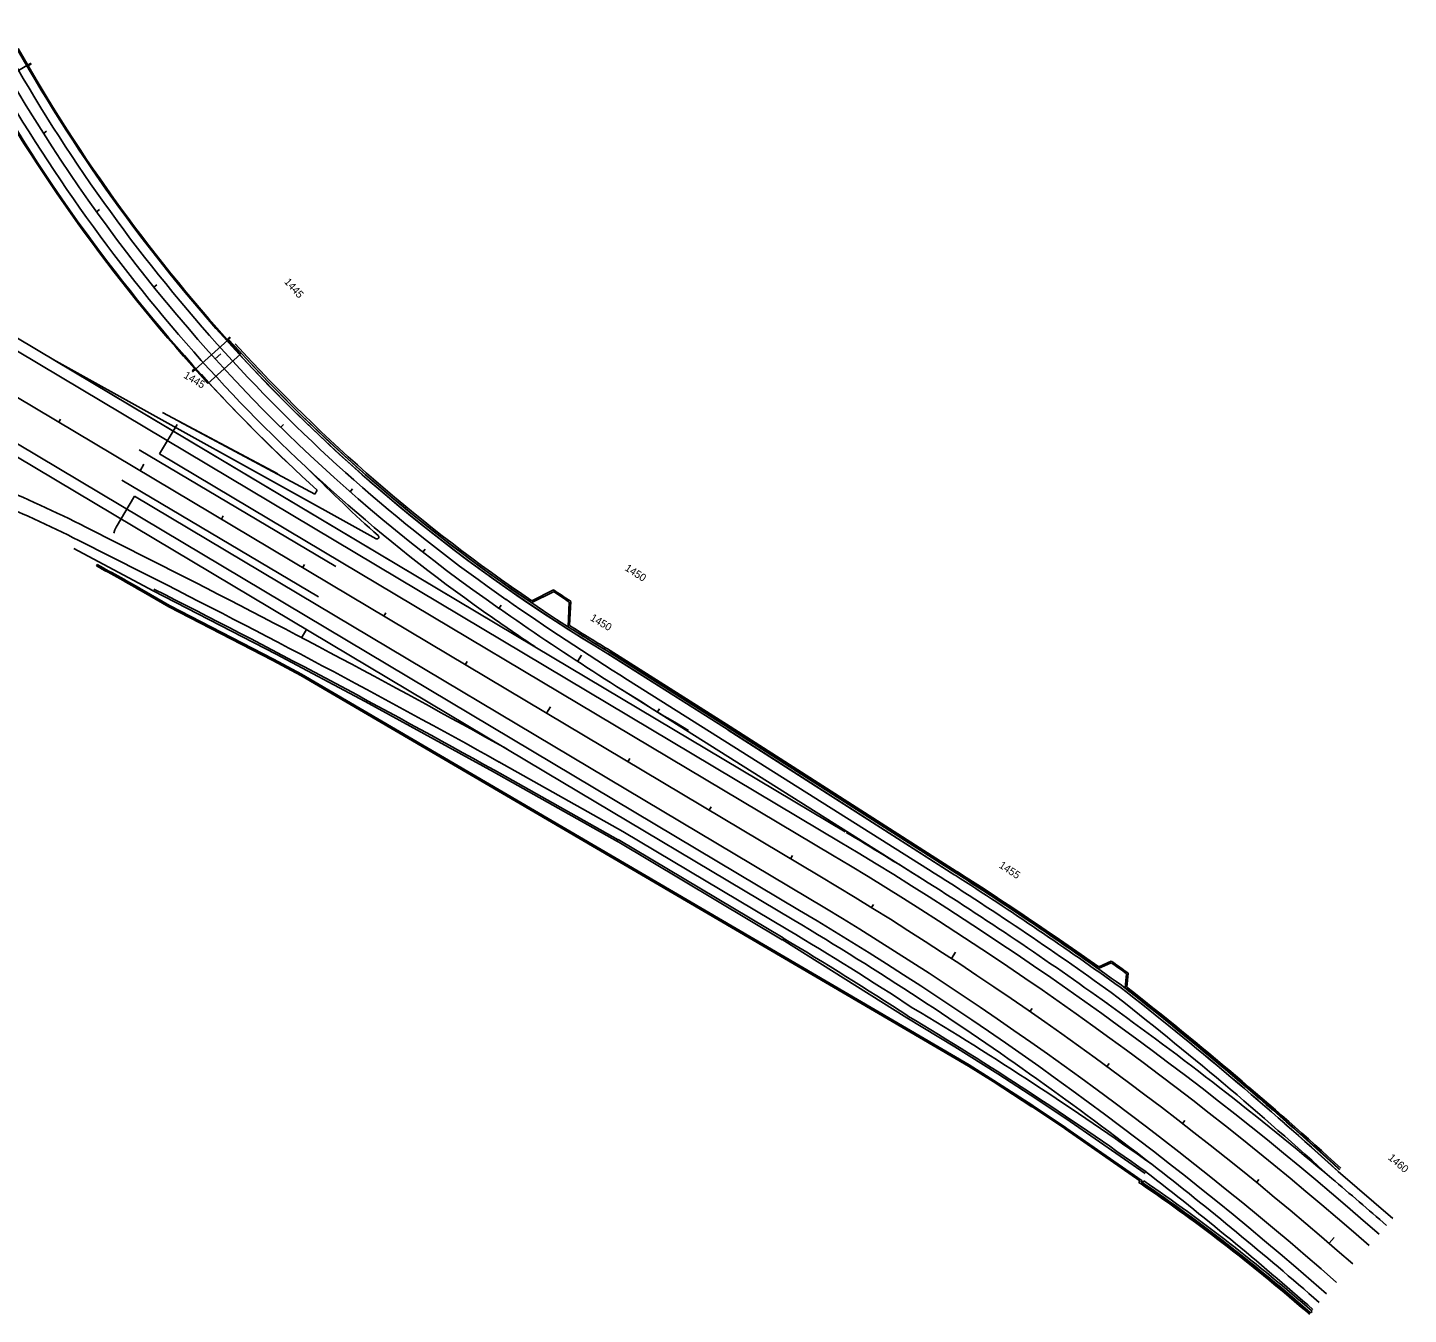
# Model space of a CAD drawing. Extents: x 2339272 to 2351734, y 366540 to 375057.
# Drawn here: x 2350276 to 2351734, y 366540 to 367900 of the extents above; entities that cross this region are included whole.
import ezdxf

# ---------------------------------------------------------------- set-up
doc = ezdxf.new("R2010")
doc.units = 0
for name, color, linetype in [('RD_HC_Cl', 7, 'Continuous'), ('RD_HC_Data_Tic', 7, 'Continuous'), ('RD_HC_TX_Sta50', 7, 'Continuous'), ('RD_PD_Bridge', 7, 'Continuous'), ('RD_PD_Final_LnLine', 7, 'Continuous'), ('RD_PD_Final_TrvlWay', 7, 'Continuous'), ('RD_PD_GR', 7, 'Continuous'), ('RD_PD_GrRail', 7, 'Continuous'), ('RD_PD_MedBWall', 7, 'Continuous'), ('RD_PD_NOISE-WALL-GM', 7, 'Continuous'), ('RD_PD_PaveShd', 7, 'Continuous')]:
    doc.layers.add(name, color=color, linetype=linetype)

msp = doc.modelspace()

# ---------------------------------------------------------------- linework, layer by layer
at = {"layer": 'RD_HC_Cl'}
msp.add_line((2346281.6, 369885.4), (2351112.4, 367003.2), dxfattribs=at)
for centre, radius, start, end in [((2351779.9, 368732.5), 1762, 199.588, 235.1808), ((2352718.5, 370082.1), 3405.9, 235.1808, 239.1785), ((2349155.3, 363723), 3819.7, 48.7231, 59.1785)]:
    msp.add_arc(centre, radius, start, end, dxfattribs=at)
at = {"layer": 'RD_HC_Data_Tic'}
for p, q in [((2350292.2, 367788.2), (2350295.6, 367790.4)), ((2350348.2, 367705.4), (2350351.4, 367707.7)), ((2350408.8, 367625.8), (2350411.9, 367628.3)), ((2350473.7, 367549.8), (2350479.7, 367555.2)), ((2350308.4, 367482.9), (2350310.4, 367486.3)), ((2350542.9, 367477.6), (2350545.7, 367480.5)), ((2350394.3, 367431.7), (2350398.4, 367438.5)), ((2350616.1, 367409.5), (2350618.7, 367412.5)), ((2350480.2, 367380.4), (2350482.2, 367383.9)), ((2350693, 367345.6), (2350695.5, 367348.7)), ((2350566, 367329.2), (2350568.1, 367332.6)), ((2350651.9, 367278), (2350654, 367281.4)), ((2350773.4, 367286.2), (2350775.7, 367289.5)), ((2350856.3, 367230.3), (2350860.7, 367237)), ((2350737.8, 367226.7), (2350739.8, 367230.2)), ((2350823.7, 367175.5), (2350827.8, 367182.4)), ((2350940.9, 367176.8), (2350942.9, 367180.3)), ((2350909.5, 367124.3), (2350911.6, 367127.7)), ((2350995.4, 367073), (2350997.5, 367076.5)), ((2351081.3, 367021.8), (2351083.3, 367025.2)), ((2351166.9, 366970.1), (2351169, 366973.5)), ((2351251.2, 366916.3), (2351255.6, 366923)), ((2351334.1, 366860.4), (2351336.4, 366863.6)), ((2351415.5, 366802.3), (2351417.8, 366805.5)), ((2351495.3, 366742), (2351497.7, 366745.2)), ((2351573.5, 366679.7), (2351576, 366682.8)), ((2351650.1, 366615.4), (2351655.3, 366621.5))]:
    msp.add_line(p, q, dxfattribs=at)
at = {"layer": 'RD_PD_Bridge'}
for p, q in [((2350235.5, 367837.1), (2350275.5, 367860.3)), ((2350486.9, 367569.7), (2350452.6, 367538.8)), ((2350500.4, 367554.9), (2350466, 367524))]:
    msp.add_line(p, q, dxfattribs=at)
for points in [[(2350275.5, 367860.3), (2350278.6, 367862.1), (2350279.1, 367861.2), (2350276, 367859.4)], [(2350486.3, 367570.4), (2350488.9, 367572.8), (2350489.5, 367572), (2350486.9, 367569.7)], [(2350449.3, 367537.2), (2350451.9, 367539.5), (2350452.6, 367538.8), (2350450, 367536.4)]]:
    msp.add_lwpolyline(points, close=True, dxfattribs=at)
for radius, start, end in [(1740, 209.4445, 222.6246), (1738.9, 209.4445, 222.6246), (1785.1, 209.4615, 222.6075), (1784, 209.4611, 222.6079)]:
    msp.add_arc((2351779.9, 368732.5), radius, start, end, dxfattribs=at)
at = {"layer": 'RD_PD_Final_LnLine'}
for p, q in [((2348620.9, 368538.6), (2351133.9, 367039.3)), ((2348577.9, 368466.5), (2351090.9, 366967.2)), ((2350811.2, 367245.8), (2351138.9, 367050.3)), ((2350902.7, 367200.6), (2351220.6, 367000.2))]:
    msp.add_line(p, q, dxfattribs=at)
for centre, radius, start, end in [((2351779.9, 368732.5), 1762, 199.588, 235.1808), ((2349155.3, 363723), 3873.7, 57.7811, 59.1785), ((2349155.3, 363723), 3861.7, 48.7231, 59.1785), ((2349155.3, 363723), 3873.7, 54.29, 57.7811), ((2349155.3, 363723), 3777.7, 48.7231, 59.1785), ((2349155.3, 363723), 3873.7, 49.8519, 54.3519)]:
    msp.add_arc(centre, radius, start, end, dxfattribs=at)
at = {"layer": 'RD_PD_Final_TrvlWay'}
for p, q in [((2348626.9, 368549), (2350811.2, 367245.8)), ((2350103.9, 367542), (2350822.6, 367113.2)), ((2350103.9, 367542), (2350822.6, 367113.2)), ((2350302.4, 367549.4), (2350643.5, 367359.8)), ((2350302.4, 367549.4), (2350811.2, 367245.8)), ((2350336.9, 367372.1), (2350405.2, 367337.7)), ((2350329.7, 367357.9), (2350398, 367323.4)), ((2350570, 367263.9), (2350564.9, 367255.3)), ((2350909.1, 367210.7), (2351227, 367010.4)), ((2350773.4, 367124), (2350904.3, 367050.5)), ((2351084.7, 366956.8), (2350822.6, 367113.2)), ((2350904.3, 367050.5), (2351078.6, 366946.5))]:
    msp.add_line(p, q, dxfattribs=at)
for centre, radius, start, end in [((2351779.9, 368732.5), 1750, 210.0316, 235.1808), ((2351779.9, 368732.5), 1774, 210.1344, 235.1808), ((2349688.3, 366086.1), 1440.4, 63.2362, 71.7499), ((2349688.3, 366086.1), 1424.4, 63.2362, 71.7499), ((2351833.7, 368686), 1778, 224.8537, 228.0761), ((2350644.5, 367361.6), 2, 239.1785, 50.3687), ((2345894.9, 358394.7), 10016, 60.79784, 63.23618), ((2345894.9, 358394.7), 10000, 60.80043, 63.23618), ((2352718.5, 370082.1), 3393.9, 235.1808, 237.7811), ((2352718.5, 370082.1), 3417.9, 235.1808, 236.079), ((2349155.3, 363723), 3885.7, 54.3519, 57.7811), ((2349155.3, 363723), 3765.7, 56.801, 59.1785), ((2349155.3, 363723), 3753.7, 56.801, 59.1785), ((2349155.3, 363723), 3765.7, 52.2219, 56.801), ((2349034.7, 363816.8), 3882.7, 47.5978, 52.0978), ((2349282.2, 363643.5), 3753.7, 54.4856, 59.0867), ((2349155.3, 363723), 3765.7, 48.7231, 52.2109), ((2349155.3, 363723), 3873.7, 48.7231, 49.8519)]:
    msp.add_arc(centre, radius, start, end, dxfattribs=at)
at = {"layer": 'RD_PD_GR'}
msp.add_line((2351659.7, 366691.4), (2351717.4, 366641.7), dxfattribs=at)
msp.add_arc((2351779.9, 368732.5), 1784, 222.2353, 226.3672, dxfattribs=at)
at = {"layer": 'RD_PD_GrRail'}
for p, q in [((2350417.9, 367493.3), (2350539.8, 367428.3)), ((2350600.9, 367330.5), (2350393.4, 367453.9)), ((2350375.1, 367421.8), (2350582.7, 367298.4)), ((2350408.1, 367304.9), (2350324.2, 367349.5)), ((2350538, 367237.9), (2350408.1, 367304.9)), ((2350632, 367187.9), (2350537.9, 367237.9)), ((2350767.5, 367113.5), (2350632, 367187.9)), ((2350898.4, 367040.1), (2350767.5, 367113.5)), ((2351072.4, 366936.2), (2350898.1, 367040.2)), ((2351204.3, 366853.8), (2351072.4, 366936.3)), ((2351254.9, 366823), (2351204.3, 366853.8)), ((2351300.4, 366794.3), (2351254.9, 366823.1)), ((2351341.5, 366767.7), (2351300.3, 366794.3)), ((2351376.8, 366744.1), (2351341.5, 366767.7)), ((2351455.7, 366689.2), (2351376.8, 366744.1))]:
    msp.add_line(p, q, dxfattribs=at)
at = {"layer": 'RD_PD_MedBWall'}
for p, q in [((2350888.5, 367238.1), (2351015.4, 367157.8)), ((2350889.7, 367240.1), (2351016.6, 367159.7)), ((2351255, 367004.4), (2351015.4, 367157.8)), ((2351256.3, 367006.4), (2351016.6, 367159.7)), ((2351454.5, 366681.3), (2351453.2, 366679.4)), ((2351632.1, 366543.5), (2351630.6, 366541.8))]:
    msp.add_line(p, q, dxfattribs=at)
for centre, radius, start, end in [((2351779.9, 368732.5), 1740, 221.9656, 239.1829), ((2351779.9, 368732.5), 1737.7, 221.9656, 239.1839), ((2349155.3, 363723), 3895.7, 54.2871, 57.3854), ((2349155.3, 363723), 3898.1, 54.2864, 57.3854), ((2349068, 363859.6), 3838.7, 47.5354, 52.0384), ((2349068, 363859.6), 3841.1, 47.5354, 52.039), ((2350413.3, 365155.9), 1844.6, 48.7061, 55.6838), ((2350413.3, 365155.9), 1846.9, 48.7061, 55.6838)]:
    msp.add_arc(centre, radius, start, end, dxfattribs=at)
at = {"layer": 'RD_PD_NOISE-WALL-GM'}
for p, q in [((2350348.9, 367332.5), (2350348.2, 367331.1)), ((2350397.9, 367303.5), (2350424.6, 367287.9)), ((2350398.7, 367304.8), (2350425.4, 367289.2)), ((2350807.5, 367292.3), (2350830.9, 367303.9)), ((2350808.1, 367294.3), (2350831, 367305.7)), ((2350846.3, 367266.9), (2350847.6, 367293)), ((2350847.9, 367268.2), (2350849.2, 367293.7)), ((2350534.4, 367231.3), (2350424.6, 367287.9)), ((2350535.1, 367232.6), (2350425.3, 367289.2)), ((2350890, 367240.5), (2351016.9, 367160.1)), ((2350890.8, 367241.8), (2351017.7, 367161.4)), ((2350564.2, 367215.4), (2350534.4, 367231.3)), ((2350564.9, 367216.7), (2350535.1, 367232.6)), ((2350564.2, 367215.5), (2351269.3, 366802.7)), ((2350564.9, 367216.7), (2351270.1, 366804)), ((2351256.6, 367006.8), (2351016.9, 367160.1)), ((2351257.4, 367008), (2351017.7, 367161.4)), ((2351406.8, 366907.5), (2351420.1, 366913.6)), ((2351406.7, 366905.7), (2351420, 366911.8)), ((2351434.9, 366885.4), (2351436.3, 366900.2)), ((2351436.4, 366886.1), (2351437.8, 366900.9)), ((2351295.3, 366786.3), (2351269.2, 366802.7)), ((2351296.1, 366787.6), (2351270.1, 366804)), ((2351336.3, 366759.7), (2351295.2, 366786.4)), ((2351337.1, 366760.9), (2351296, 366787.6)), ((2351337.1, 366760.9), (2351296, 366787.6)), ((2351371.6, 366736.2), (2351336.2, 366759.8)), ((2351372.4, 366737.4), (2351337, 366761)), ((2351452.8, 366681.5), (2351372.2, 366737.5)), ((2351450.2, 366681.4), (2351371.4, 366736.3)), ((2351449.1, 366679.8), (2351450.2, 366681.4)), ((2351451.7, 366679.9), (2351452.8, 366681.5))]:
    msp.add_line(p, q, dxfattribs=at)
for centre, radius, start, end in [((2351779.9, 368732.5), 1737.7, 222.2353, 235.973), ((2351779.9, 368732.5), 1735.7, 222.2353, 235.9535), ((2349688.3, 366086.1), 1409.1, 59.7618, 62.0763), ((2349688.3, 366086.1), 1410.6, 59.7618, 62.0763), ((2351779.9, 368732.5), 1715, 236.4035, 237.0722), ((2351779.9, 368732.5), 1713.5, 236.3746, 237.1012), ((2351779.9, 368732.5), 1737.7, 237.5028, 239.1839), ((2351779.9, 368732.5), 1735.7, 237.5222, 239.1839), ((2349155.3, 363723), 3898.6, 54.7259, 57.3854), ((2349155.3, 363723), 3900.1, 54.7386, 57.3854), ((2349155.3, 363723), 3912.7, 54.3128, 54.6311), ((2349155.3, 363723), 3911.2, 54.3254, 54.6184), ((2349068, 363859.6), 3841.6, 47.5354, 51.9667), ((2349068, 363859.6), 3843.1, 47.5354, 51.9545), ((2350413.3, 365155.9), 1842.6, 55.7052, 55.7965), ((2350413.3, 365155.9), 1844.1, 48.7061, 55.7319), ((2350413.3, 365155.9), 1842.6, 48.7061, 55.7052)]:
    msp.add_arc(centre, radius, start, end, dxfattribs=at)
at = {"layer": 'RD_PD_PaveShd'}
for p, q in [((2350435.5, 367483.9), (2350578.9, 367407.1)), ((2350433.6, 367480.6), (2350415, 367449.6)), ((2350415, 367449.6), (2351125.7, 367025.5)), ((2350578.9, 367407.1), (2350581.2, 367411.2)), ((2350388.5, 367404.8), (2350369.1, 367372.2)), ((2350388.5, 367404.8), (2351099.1, 366980.9)), ((2350367.5, 367369.1), (2350366.5, 367365.6)), ((2350369.1, 367372.2), (2350367.5, 367369.1)), ((2350888.6, 367238.1), (2351015.4, 367157.8)), ((2351255, 367004.4), (2351015.4, 367157.7)), ((2350768.5, 367115.2), (2350899.4, 367041.8)), ((2350899.1, 367042), (2351073.5, 366938))]:
    msp.add_line(p, q, dxfattribs=at)
for centre, radius, start, end in [((2351779.9, 368732.5), 1740, 222.2353, 239.1785), ((2351779.9, 368732.5), 1784, 222.2353, 227.785), ((2345894.9, 358394.7), 9990, 60.80043, 63.13674), ((2349155.3, 363723), 3845.7, 48.7231, 59.1785), ((2349155.3, 363723), 3895.7, 54.2871, 57.3854), ((2349155.3, 363723), 3793.7, 48.7231, 59.1785), ((2349155.3, 363723), 3793.7, 48.7231, 59.1785), ((2349155.3, 363723), 3743.7, 56.801, 59.1785), ((2349068, 363859.6), 3838.7, 47.5384, 52.0384), ((2349282.2, 363643.5), 3743.7, 54.4886, 59.0898), ((2349155.3, 363723), 3755.7, 48.7231, 52.2109)]:
    msp.add_arc(centre, radius, start, end, dxfattribs=at)

# ---------------------------------------------------------------- texts
at = {"layer": 'RD_HC_TX_Sta50'}
for s, rotation, p in [('1445', 312.1591, (2350546, 367630.9)), ('1445', 329.1785, (2350439.6, 367530.4)), ('1450', 326.8554, (2350905.6, 367327.1)), ('1450', 329.1785, (2350869, 367274.2)), ('1455', 326.7219, (2351300.7, 367013)), ('1460', 319.2219, (2351711.8, 366704.8))]:
    msp.add_text(s, height=8, rotation=rotation, dxfattribs=at).set_placement(p)

doc.saveas('drawing.dxf')
